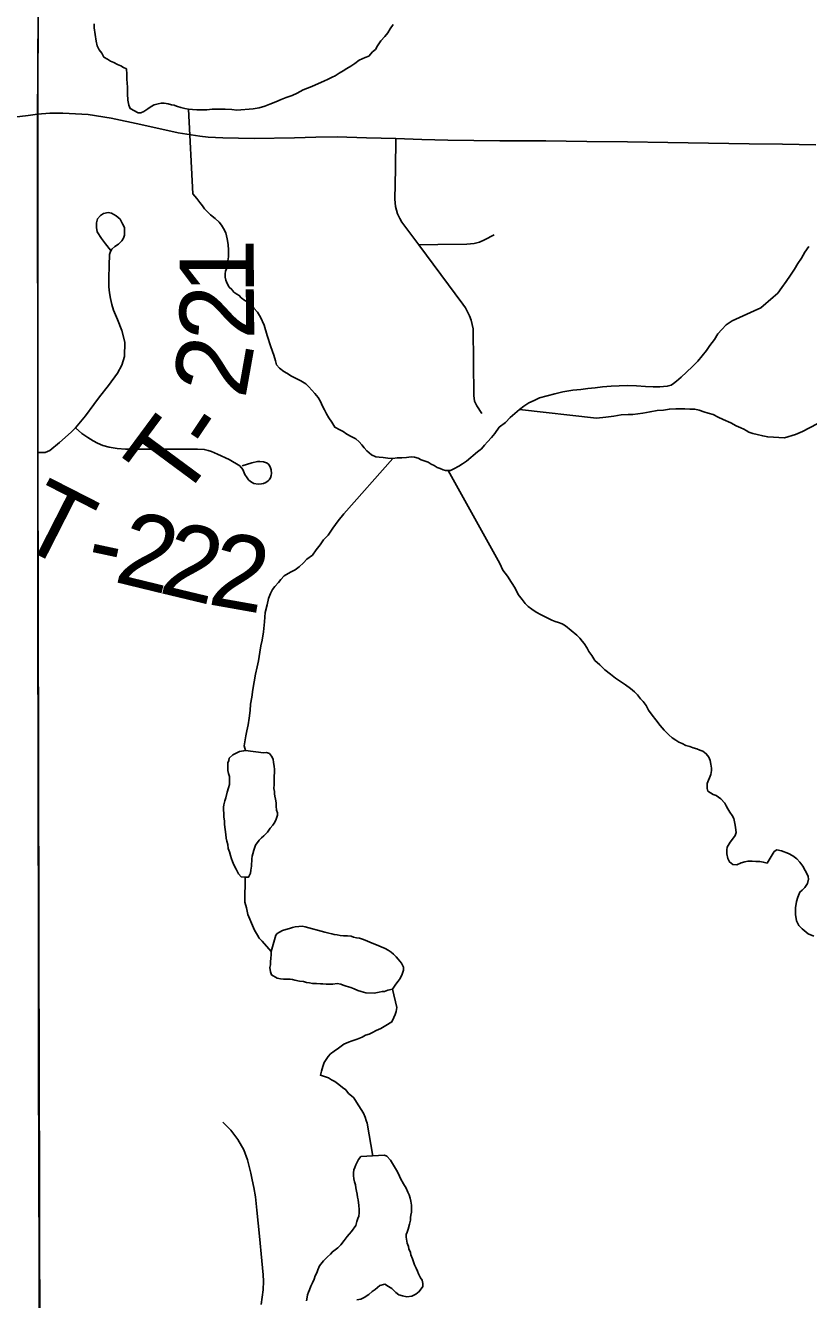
# Model space of a CAD drawing. Extents: x 103424 to 286016, y 38711 to 110967.
# Drawn here: x 119588 to 122771, y 79687 to 84863 of the extents above; entities that cross this region are included whole.
import ezdxf

# ---------------------------------------------------------------- set-up
doc = ezdxf.new("R2010")
doc.units = 0
for name, color, linetype in [('GM_X_Corporation', 7, 'Continuous'), ('GM_X_Minor_Lake', 7, 'Continuous'), ('GM_X_Minor_River', 7, 'Continuous'), ('GM_X_Township_Road', 7, 'Continuous'), ('GM_X_Township_Road_Text', 7, 'Continuous')]:
    doc.layers.add(name, color=color, linetype=linetype)

msp = doc.modelspace()

# ---------------------------------------------------------------- linework, layer by layer
at = {"layer": 'GM_X_Corporation'}
for points in [[(103423.7, 96534.8), (103423.7, 70904.9), (107977, 70917.3), (117928.9, 70934.4), (117946.9, 70934.9), (119688.2, 70990.2), (119635, 74016.7), (119631.7, 75117.1), (119628.6, 75451.2), (119621.3, 75805.1), (119622.8, 76073.8), (119627.2, 76341.1), (119628.6, 76885.8), (119631.6, 77245.6), (119644.2, 78899.8), (119644.5, 79431.3), (119642.9, 80216.4), (119641.6, 80653.5), (119641.6, 81200.9), (119640.3, 81697.7), (119639, 82590.1), (119639, 83128.3), (119639, 84504.6), (119641.6, 85722.3)], [(119688.2, 70990.2), (119635, 74016.7), (119631.7, 75117.1), (119628.6, 75451.2), (119621.3, 75805.1), (119622.8, 76073.8), (119627.2, 76341.1), (119628.6, 76885.8), (119631.6, 77245.6), (119644.2, 78899.8), (119644.5, 79431.3), (119642.9, 80216.4), (119641.6, 80653.5), (119641.6, 81200.9), (119640.3, 81697.7), (119639, 82590.1), (119639, 83128.3), (119639, 84504.6), (119641.6, 85722.3)]]:
    msp.add_lwpolyline(points, dxfattribs=at)
at = {"layer": 'GM_X_Minor_Lake'}
for points in [[(120482.7, 81917.6), (120474.6, 81915.5), (120458.5, 81913.3), (120430.4, 81898.9), (120416.4, 81886.6), (120414.5, 81876.5), (120410.6, 81866.4), (120410.8, 81852.2), (120410.9, 81836.1), (120413.1, 81824), (120417.3, 81811.9), (120417.4, 81801.8), (120417.5, 81791.7), (120417.6, 81779.6), (120413.8, 81765.4), (120407.9, 81747.2), (120402.1, 81724.9), (120398.2, 81712.7), (120394.4, 81696.5), (120392.5, 81686.4), (120392.6, 81674.3), (120394.8, 81662.2), (120395, 81646), (120397.1, 81631.9), (120397.3, 81615.8), (120399.6, 81595.6), (120401.8, 81575.4), (120404, 81561.3), (120406.2, 81549.2), (120410.4, 81535.1), (120412.6, 81519), (120416.8, 81504.9), (120421, 81490.8), (120425.2, 81476.7), (120429.4, 81466.6), (120435.6, 81452.5), (120443.9, 81434.4), (120454.2, 81416.4), (120464.4, 81404.3), (120480.6, 81402.5), (120494.7, 81402.6), (120502.6, 81418.9), (120504.5, 81431), (120506.3, 81447.2), (120506.2, 81457.3), (120508.1, 81467.4), (120508, 81477.5), (120509.9, 81487.6), (120511.8, 81497.7), (120515.7, 81511.9), (120523.5, 81532.2), (120537.4, 81552.5), (120547.4, 81562.7), (120557.4, 81570.9), (120571.4, 81585.2), (120583.3, 81601.5), (120593.3, 81613.7), (120601.2, 81625.9), (120607.1, 81638), (120613, 81654.3), (120612.9, 81664.4), (120608.7, 81674.4), (120606.5, 81690.6), (120606.4, 81704.7), (120604.2, 81718.8), (120602, 81730.9), (120599.9, 81741), (120599.8, 81751.1), (120597.6, 81763.2), (120599.4, 81779.4), (120599.2, 81799.6), (120599, 81813.7), (120600.9, 81825.9), (120600.7, 81840), (120598.6, 81854.1), (120596.4, 81868.2), (120594.2, 81882.4), (120588, 81894.4), (120579.8, 81904.4), (120567.6, 81908.4), (120555.6, 81908.2)], [(120555.6, 81908.2), (120482.7, 81917.6)], [(120606.3, 81166.4), (120587.1, 81100.5), (120587.2, 81088.4), (120585.4, 81072.2), (120583.5, 81060.1), (120583.7, 81046), (120581.8, 81035.8), (120584, 81017.7), (120588.2, 81005.6), (120610.6, 80991.7), (120624.7, 80989.8), (120636.9, 80987.9), (120651, 80988), (120663.1, 80988.2), (120673.3, 80986.2), (120683.4, 80984.3), (120701.6, 80980.5), (120717.8, 80978.6), (120729.9, 80974.7), (120742.1, 80972.8), (120754.2, 80970.9), (120770.4, 80971.1), (120786.6, 80969.2), (120796.6, 80969.3), (120810.8, 80967.4), (120822.9, 80967.5), (120837.1, 80967.7), (120855.2, 80969.9), (120869.4, 80968), (120879.5, 80964.1), (120891.7, 80960.1), (120909.9, 80954.3), (120924.1, 80948.3), (120938.3, 80942.4), (120952.5, 80938.5), (120970.8, 80932.7), (121005.1, 80931), (121025.3, 80935.2), (121037.4, 80937.4), (121047.5, 80937.4), (121061.5, 80943.7), (121079.7, 80947.9), (121093.5, 80968.2), (121103.5, 80980.4), (121111.5, 80990.6), (121119.3, 81008.9), (121125.2, 81025.1), (121125.1, 81037.2), (121116.8, 81053.3), (121102.5, 81069.3), (121094.3, 81079.3), (121084.1, 81089.3), (121073.9, 81097.3), (121061.7, 81105.3), (121049.5, 81113.2), (121033.2, 81119.1), (121015, 81127), (120996.7, 81134.9), (120978.4, 81142.8), (120962.2, 81148.7), (120946, 81154.6), (120933.8, 81156.5), (120921.7, 81158.4), (120911.6, 81162.3), (120897.4, 81164.2), (120881.2, 81164), (120867.1, 81165.9), (120854.9, 81167.8), (120842.8, 81169.7), (120832.7, 81171.7), (120820.5, 81175.6), (120804.3, 81179.5), (120790.1, 81183.3), (120739.5, 81197), (120725.3, 81200.9), (120713.1, 81202.8), (120699, 81202.6), (120684.9, 81200.5), (120672.8, 81198.4), (120660.7, 81194.2), (120646.6, 81190), (120632.6, 81185.8), (120620.5, 81179.6), (120610.5, 81173.5), (120606.3, 81166.4)], [(120606.3, 81166.4), (120587.1, 81100.5), (120587.2, 81088.4), (120585.4, 81072.2), (120583.5, 81060.1), (120583.7, 81046), (120581.8, 81035.8), (120584, 81017.7), (120588.2, 81005.6), (120610.6, 80991.7), (120624.7, 80989.8), (120636.9, 80987.9), (120651, 80988), (120663.1, 80988.2), (120673.3, 80986.2), (120683.4, 80984.3), (120701.6, 80980.5), (120717.8, 80978.6), (120729.9, 80974.7), (120742.1, 80972.8), (120754.2, 80970.9), (120770.4, 80971.1), (120786.6, 80969.2), (120796.6, 80969.3), (120810.8, 80967.4), (120822.9, 80967.5), (120837.1, 80967.7), (120855.2, 80969.9), (120869.4, 80968), (120879.5, 80964.1), (120891.7, 80960.1), (120909.9, 80954.3), (120924.1, 80948.3), (120938.3, 80942.4), (120952.5, 80938.5), (120970.8, 80932.7), (121005.1, 80931), (121025.3, 80935.2), (121037.4, 80937.4), (121047.5, 80937.4), (121061.5, 80943.7), (121079.7, 80947.9), (121093.5, 80968.2)], [(121093.5, 80968.2), (121103.5, 80980.4), (121111.5, 80990.6), (121119.3, 81008.9), (121125.2, 81025.1), (121125.1, 81037.2), (121116.8, 81053.3), (121102.5, 81069.3), (121094.3, 81079.3), (121084.1, 81089.3), (121073.9, 81097.3), (121061.7, 81105.3), (121049.5, 81113.2), (121033.2, 81119.1), (121015, 81127), (120996.7, 81134.9), (120978.4, 81142.8), (120962.2, 81148.7), (120946, 81154.6), (120933.8, 81156.5), (120921.7, 81158.4), (120911.6, 81162.3), (120897.4, 81164.2), (120881.2, 81164), (120867.1, 81165.9), (120854.9, 81167.8), (120842.8, 81169.7), (120832.7, 81171.7), (120820.5, 81175.6), (120804.3, 81179.5), (120790.1, 81183.3), (120739.5, 81197), (120725.3, 81200.9), (120713.1, 81202.8), (120699, 81202.6), (120684.9, 81200.5), (120672.8, 81198.4), (120660.7, 81194.2), (120646.6, 81190), (120632.6, 81185.8), (120620.5, 81179.6), (120610.5, 81173.5), (120606.3, 81166.4)], [(120951, 80267.1), (120942.3, 80255.7), (120930.4, 80233.3), (120926.5, 80223.2), (120922.6, 80213), (120920.7, 80200.9), (120920.8, 80190.8), (120923, 80176.7), (120925.1, 80164.6), (120929.3, 80152.5), (120931.5, 80140.4), (120933.7, 80126.3), (120935.8, 80114.2), (120938, 80102.1), (120940.1, 80092), (120942.3, 80079.9), (120942.4, 80069.8), (120944.6, 80051.7), (120944.8, 80039.5), (120942.9, 80025.4), (120939, 80015.2), (120935.1, 80003.1)], [(120934.7, 79685.9), (120950.9, 79688.1), (120964.9, 79694.3), (120983, 79706.6), (120996.9, 79718.9), (121009, 79727.1), (121029, 79743.4), (121049.1, 79749.7), (121063.4, 79739.7), (121077.6, 79731.8), (121093.9, 79715.8), (121106.2, 79705.8), (121120.4, 79701.9), (121138.6, 79698.1), (121158.7, 79700.3), (121174.8, 79708.5), (121188.8, 79718.8), (121202.7, 79739.1), (121202.6, 79751.2), (121200.4, 79765.3), (121194.2, 79775.4), (121186, 79791.5), (121181.8, 79801.5), (121175.6, 79813.6), (121169.4, 79827.7), (121165.2, 79839.7), (121161, 79851.8), (121154.8, 79867.9), (121152.6, 79878), (121146.4, 79892.1), (121144.3, 79902.1), (121140.1, 79916.2), (121135.8, 79940.4), (121135.6, 79950.5), (121139.6, 79960.7), (121143.5, 79972.8), (121149.3, 79993.1), (121153.1, 80009.3), (121153, 80019.4), (121154.9, 80029.5), (121156.8, 80041.7), (121156.6, 80057.8), (121156.5, 80069.9), (121154.3, 80086.1), (121152.1, 80098.2), (121147.9, 80112.3), (121141.7, 80122.3), (121135.5, 80138.4), (121125.2, 80156.5), (121112.8, 80178.6), (121104.5, 80196.7), (121096.3, 80212.8), (121071.5, 80252.9), (121057.2, 80268.9), (121047.1, 80272.9), (120951, 80267.1)], [(120935.1, 80003.1), (120931.2, 79986.9), (120913.3, 79962.5), (120903.4, 79952.3), (120895.4, 79942.1), (120883.5, 79925.8), (120869.5, 79909.5), (120857.5, 79897.3), (120847.5, 79889.1), (120835.5, 79880.9), (120827.6, 79870.7), (120815.6, 79860.5), (120799.6, 79844.2), (120783.7, 79823.8), (120775.8, 79807.6), (120771.9, 79795.4), (120766, 79783.2), (120762.1, 79769.1), (120754.2, 79754.8), (120748.3, 79740.6), (120742.4, 79726.5), (120738.5, 79716.3), (120734.5, 79706.2), (120732.6, 79696), (120730.8, 79681.9)]]:
    msp.add_lwpolyline(points, dxfattribs=at)
at = {"layer": 'GM_X_Minor_River'}
for points in [[(119866.8, 84868.8), (119867, 84852.7), (119875.7, 84798.2), (119880, 84780.1), (119888.2, 84764), (119898.5, 84750), (119906.8, 84733.9), (119921, 84725.9), (119933.2, 84718), (119947.4, 84712.1), (119961.6, 84704.1), (119975.8, 84698.2), (119986, 84692.3), (119998.2, 84686.3), (120000.5, 84664.1), (120000.7, 84643.9), (120003.1, 84611.6), (120003.4, 84585.4), (120003.7, 84559.1), (120008, 84538.9), (120014.2, 84524.9), (120046.7, 84507), (120056.8, 84507.1), (120068.9, 84513.3), (120084.9, 84523.5), (120098.9, 84533.8), (120111, 84540), (120127.1, 84544.2), (120139.2, 84546.3), (120151.3, 84546.4), (120167.5, 84544.6), (120181.7, 84540.7), (120191.8, 84538.8), (120201.9, 84534.8), (120220.2, 84528.9), (120236.4, 84525.1), (120250.5, 84523.2), (120266.7, 84521.3), (120284.9, 84519.5), (120305.1, 84519.7), (120325.3, 84519.9), (120347.5, 84522.1), (120371.7, 84522.4), (120400, 84522.6), (120426.3, 84520.9), (120446.5, 84519.1), (120513.1, 84523.8), (120537.3, 84528), (120561.4, 84534.3), (120581.5, 84542.6), (120605.7, 84553), (120627.8, 84561.3), (120647.9, 84569.5), (120672, 84577.9), (120692.1, 84588.2), (120716.2, 84600.5), (120752.4, 84615), (120778.5, 84627.4), (120800.6, 84635.7), (120818.7, 84644), (120834.7, 84652.2), (120846.8, 84658.4), (120862.8, 84668.6), (120878.9, 84678.9), (120894.9, 84687.1), (120911, 84697.4), (120927, 84707.7), (120945, 84722), (120969.1, 84732.3), (120983.2, 84738.5), (120999.2, 84754.8), (121011.2, 84765.1), (121019.1, 84779.3), (121033, 84799.6), (121048.9, 84818), (121060.9, 84832.2), (121070.8, 84848.5), (121082.7, 84866.8)], [(120250.5, 84523.2), (120268.7, 84177.9), (120285, 84159.9), (120297.3, 84143.9), (120307.6, 84129.8), (120315.8, 84117.8), (120328.1, 84105.8), (120340.3, 84093.8), (120358.7, 84077.8), (120375, 84063.8), (120385.3, 84051.8), (120393.5, 84037.8), (120401.8, 84019.7), (120408.1, 83995.5), (120412.4, 83973.3), (120412.7, 83949.1), (120413, 83922.8), (120411.2, 83906.6), (120407.3, 83890.4), (120405.5, 83874.3), (120401.6, 83864.1), (120399.7, 83854), (120399.8, 83839.9), (120402, 83827.8), (120408.2, 83813.7), (120416.5, 83799.6), (120426.7, 83789.6), (120434.9, 83779.6), (120447.1, 83771.6), (120457.2, 83765.7), (120465.4, 83755.7), (120479.7, 83745.7), (120491.9, 83737.8), (120506.2, 83727.8), (120516.4, 83713.8), (120530.7, 83697.7), (120543.1, 83677.7), (120557.6, 83645.5), (120570.2, 83603.2), (120584.9, 83556.9), (120597.4, 83522.7), (120603.7, 83500.5), (120607.9, 83484.4), (120620.2, 83470.4), (120638.6, 83456.4), (120650.7, 83450.5), (120669.1, 83438.5), (120707.7, 83418.7), (120728, 83406.8), (120740.3, 83394.8), (120752.5, 83380.8), (120764.8, 83366.8), (120777.1, 83350.7), (120787.4, 83334.7), (120795.7, 83316.6), (120804, 83300.5), (120812.2, 83284.4), (120820.5, 83268.3), (120832.8, 83250.3), (120845.2, 83230.2), (120865.5, 83220.3), (120879.7, 83212.4), (120894, 83202.4), (120912.3, 83192.5), (120930.6, 83182.6), (120944.8, 83170.6), (120955.1, 83158.6), (120965.3, 83146.5), (120975.5, 83134.5), (120993.9, 83118.5), (121012.2, 83110.6), (121026.3, 83108.8), (121042.5, 83106.9), (121060.7, 83105.1), (121080.9, 83103.3), (121099.1, 83105.5), (121117.2, 83105.6), (121137.4, 83107.9), (121155.6, 83110), (121169.7, 83108.2), (121183.9, 83104.3), (121196.1, 83098.3), (121212.3, 83092.4), (121224.5, 83088.5), (121236.7, 83080.6), (121248.9, 83074.6), (121261.1, 83066.7), (121273.3, 83062.8), (121285.5, 83056.8), (121295.6, 83054.9), (121305.7, 83055), (121315.8, 83055.1), (121329.8, 83061.3), (121349.9, 83071.6), (121363.9, 83081.8), (121380, 83092.1), (121426, 83130.9), (121442, 83143.2)], [(121442, 83143.2), (121453.9, 83157.5), (121465.9, 83171.7), (121481.9, 83188), (121495.8, 83204.3), (121513.7, 83230.8), (121539.7, 83249.2), (121557.7, 83269.6), (121577.7, 83286), (121595.7, 83302.3), (121613.7, 83316.6), (121633.7, 83328.9), (121655.8, 83339.2), (121677.9, 83349.6), (121708.1, 83358), (121740.3, 83366.4), (121772.6, 83374.8), (121812.9, 83381.2), (121845.2, 83383.6), (121873.4, 83387.9), (121903.7, 83390.2), (121933.9, 83394.5), (121968.2, 83396.9), (122000.5, 83399.2), (122036.8, 83399.6), (122071.2, 83397.9), (122107.6, 83396.3), (122139.9, 83394.6), (122166.2, 83394.8), (122196.4, 83397.1), (122212.5, 83401.4), (122222.6, 83407.5), (122234.6, 83417.7), (122252.6, 83434.1), (122274.5, 83454.5), (122298.5, 83476.9), (122320.5, 83499.4), (122338.4, 83519.8), (122356.3, 83542.2), (122370.2, 83562.5), (122388.1, 83586.9), (122402, 83609.3), (122417.9, 83627.6), (122435.9, 83646), (122460, 83662.4), (122490.1, 83676.8), (122520.2, 83689.2), (122550.4, 83703.7), (122576.5, 83716.1), (122626.5, 83759), (122646.5, 83775.3), (122662.4, 83797.7), (122680.3, 83822.1), (122698.1, 83848.6), (122714, 83873), (122727.9, 83895.3), (122741.8, 83917.7), (122755.6, 83942.1), (122771.5, 83964.4)], [(121595.7, 83302.3), (121909.1, 83267), (121947.5, 83271.5), (121979.7, 83275.8), (122009.9, 83280.1), (122038.2, 83282.5), (122056.4, 83282.6), (122096.7, 83287.1), (122126.9, 83293.4), (122155.2, 83297.7), (122181.4, 83300), (122205.6, 83304.3), (122231.8, 83304.6), (122250, 83304.8), (122268.2, 83304.9), (122288.4, 83303.1), (122308.6, 83303.3), (122326.8, 83299.5), (122345.1, 83293.6), (122363.3, 83287.7), (122383.6, 83281.8), (122403.9, 83271.9), (122424.2, 83262), (122454.7, 83248.2), (122477, 83236.3), (122495.3, 83228.4), (122507.5, 83222.5), (122517.6, 83216.5), (122527.8, 83210.6), (122544, 83204.7), (122562.3, 83200.8), (122584.5, 83195), (122604.8, 83191.1), (122673.5, 83187.8), (122717.8, 83200.3), (122745.9, 83212.7), (122806.1, 83243.6)], [(121080.9, 83103.3), (120881.6, 82879.1), (120859.7, 82850.6), (120837.8, 82820), (120817.9, 82791.6), (120800, 82773.2), (120786.1, 82752.9), (120770.2, 82732.5), (120754.3, 82710.1), (120732.2, 82693.8), (120718.2, 82679.5), (120700.3, 82663.1), (120684.3, 82650.9), (120668.2, 82642.6), (120656.1, 82636.4), (120640.1, 82626.2), (120626.1, 82611.9), (120616.2, 82599.7), (120602.2, 82583.4), (120592.3, 82571.2), (120584.4, 82554.9), (120576.5, 82534.6), (120570.8, 82508.3), (120563, 82478), (120559.5, 82439.5), (120555.9, 82399.1), (120550.2, 82364.7), (120544.4, 82342.4), (120540.7, 82316.1), (120535, 82281.7), (120529.3, 82257.4), (120523.5, 82227.1), (120517.8, 82196.7), (120512.2, 82164.3), (120508.5, 82134), (120502.7, 82105.7), (120501, 82079.4), (120497.3, 82049), (120493.6, 82020.7), (120487.9, 81996.4), (120484, 81976.2), (120476.4, 81935.7), (120482.7, 81917.6)], [(121305.7, 83055), (121516.1, 82677.3), (121528.5, 82649.2), (121547, 82625.1), (121563.4, 82599), (121577.8, 82576.9), (121590.2, 82550.8), (121606.6, 82530.7), (121618.9, 82514.7), (121631.2, 82502.7), (121645.5, 82490.7), (121663.8, 82478.8), (121684.1, 82468.9), (121706.4, 82457), (121726.8, 82447.1), (121741, 82441.2), (121755.1, 82437.3), (121769.3, 82431.4), (121783.6, 82423.4), (121828.5, 82385.5), (121840.7, 82373.5), (121850.9, 82361.5), (121859.1, 82351.5), (121871.5, 82333.4), (121877.7, 82319.3), (121890, 82303.3), (121902.3, 82283.2), (121922.8, 82265.2), (121943.2, 82245.2), (121965.6, 82227.3), (121986, 82211.3), (122006.3, 82197.4), (122026.7, 82183.4), (122047.1, 82169.5), (122063.4, 82155.5), (122075.6, 82143.5), (122088, 82127.5), (122098.2, 82115.5), (122110.5, 82099.4), (122120.8, 82081.4), (122135.2, 82061.3), (122149.5, 82041.2), (122168, 82019.2), (122184.4, 81999.2), (122202.8, 81981.2), (122217, 81969.2), (122231.3, 81959.2), (122243.5, 81951.3), (122257.7, 81945.4), (122271.9, 81937.4), (122288.1, 81933.5), (122302.3, 81927.6), (122316.5, 81923.7), (122328.7, 81917.8), (122340.9, 81913.9), (122355.1, 81903.9), (122365.4, 81889.9), (122371.6, 81875.8), (122373.8, 81861.7), (122376, 81845.5), (122376.1, 81835.4), (122374.3, 81819.3), (122358.5, 81782.7), (122358.8, 81762.5), (122360.9, 81752.5), (122383.3, 81738.6), (122395.5, 81734.6), (122413.8, 81720.7), (122430.2, 81702.6), (122436.3, 81692.6), (122442.5, 81680.6), (122450.8, 81666.5), (122461, 81652.5), (122467.2, 81640.4), (122471.5, 81620.2), (122473.7, 81606.1), (122475.9, 81594), (122476, 81583.9), (122472.1, 81571.8), (122462.1, 81557.5), (122452.2, 81545.3), (122440.3, 81525), (122438.4, 81512.9), (122438.6, 81496.7), (122442.9, 81478.5), (122449.1, 81464.5), (122463.3, 81454.5), (122479.5, 81452.7), (122497.6, 81460.9), (122511.7, 81465.1), (122523.8, 81467.2), (122542, 81467.4), (122556.1, 81465.5), (122572.3, 81465.7), (122586.4, 81463.8), (122602.6, 81459.9), (122630.4, 81506.7), (122642.4, 81512.9), (122660.6, 81509), (122689, 81499.2), (122707.3, 81489.3)], [(122707.3, 81489.3), (122723.6, 81477.3), (122735.9, 81463.3), (122748.2, 81447.3), (122756.5, 81429.2), (122764.7, 81415.1), (122768.9, 81405), (122771, 81395), (122767.2, 81376.7), (122755.3, 81360.5), (122745.3, 81350.3), (122735.3, 81342.1), (122727.4, 81321.8), (122721.6, 81303.6), (122717.9, 81277.3), (122718.1, 81251), (122722.5, 81224.8), (122730.8, 81206.7), (122745.1, 81192.7), (122769.6, 81172.7), (122791.9, 81162.9)], [(120480.6, 81402.5), (120479.7, 81301.5), (120486.1, 81277.3), (120492.4, 81251.1), (120515.3, 81196.8), (120519.4, 81186.7), (120531.8, 81166.6), (120538, 81154.6), (120550.3, 81142.6), (120587.1, 81100.5)], [(121097.1, 80872.8), (121079.7, 80947.9)], [(121097.1, 80872.8), (121094.8, 80857.1), (121090.9, 80845), (121085, 80832.8), (121077.2, 80814.5), (121053.1, 80800.1), (121033, 80787.8), (121012.9, 80779.5), (120998.9, 80771.3), (120984.8, 80765.1), (120970.7, 80760.9), (120956.7, 80752.7), (120936.6, 80744.4), (120916.5, 80738.2), (120900.4, 80732), (120882.3, 80723.7), (120860.3, 80707.3), (120842.2, 80695), (120828.2, 80684.8), (120818.2, 80674.6), (120810.3, 80662.4), (120802.4, 80650.2), (120796.5, 80634), (120790.7, 80613.7), (120786.8, 80597.5), (120807.1, 80591.7), (120819.2, 80587.7), (120831.5, 80579.8), (120845.7, 80571.8), (120862, 80559.9), (120876.3, 80547.9), (120890.5, 80537.9), (120900.8, 80523.9), (120913, 80513.9), (120923.2, 80505.9), (120933.5, 80487.9), (120962.3, 80443.7), (120968.5, 80427.6), (120972.7, 80413.5), (120976.9, 80403.5), (121000.1, 80269.1)]]:
    msp.add_lwpolyline(points, dxfattribs=at)
at = {"layer": 'GM_X_Township_Road'}
for points in [[(119644.5, 78894.7), (119645, 79059.8), (119645.4, 79224.9), (119645.9, 79373.4), (119646.3, 79522), (119645.9, 79687), (119645.6, 79852.1), (119644.6, 80290.5), (119644.2, 80455.6), (119643.7, 80620.6), (119643.3, 80785.7), (119642.8, 80950.8), (119642.1, 81199.9), (119640.9, 81860.2), (119638.6, 83127.2), (119637.6, 84501.8), (119638.3, 84666.9), (119639.1, 84831.9), (119639.6, 84957.7)], [(119483.7, 84483.4), (119598.7, 84496.6), (119637.6, 84501.8)], [(119637.6, 84501.8), (119687.6, 84506.5), (119740.2, 84505.8), (119843.3, 84500.2), (119936.2, 84486.4), (120057, 84460), (120208.9, 84426.5), (120296.2, 84413.2), (120331, 84409.2), (120390.5, 84406.1), (120517.2, 84403.3), (120682.2, 84406.7), (120768.5, 84408.5), (120854.9, 84410.2), (120974, 84406.5), (121093.2, 84402.8), (121199.1, 84399.6), (121305.1, 84396.4), (121410.8, 84394.8), (121516.5, 84393.3), (121609.5, 84393.8), (121702.6, 84394.3), (121786, 84393.1), (121869.4, 84391.8), (122034.4, 84389.3), (122199.5, 84386.8), (122364.5, 84384.3), (122529.5, 84381.8), (122664.9, 84379.7), (122800.4, 84377.7)], [(121443.3, 83286.7), (121422, 83317.1), (121413.8, 83336.6), (121409.9, 83358.8), (121407.4, 83630.1), (121404.2, 83647.9), (121399.2, 83665.4), (121392.9, 83682.5), (121385.3, 83699), (121376.3, 83714.8), (121366, 83729.8), (121276.2, 83850.6), (121186.4, 83971.4), (121117.9, 84063.5), (121109.4, 84077.7), (121100.6, 84097.4), (121095.8, 84111.8), (121092.5, 84126.7), (121090.5, 84141.9), (121090, 84157.1), (121091.6, 84279.9), (121093.2, 84402.8)], [(119638.6, 83127.2), (119667.8, 83128), (119687.5, 83136), (119726.6, 83168.8), (119774.4, 83209.8), (119791.5, 83228.4), (119832.3, 83276.9), (119866, 83323.2), (119888.4, 83353.3), (119925.9, 83399.9), (119962.1, 83450.5), (119979.8, 83483.1), (119990.6, 83518.4), (119991.4, 83575.9), (119979.4, 83622.9), (119961.5, 83668.2), (119946.5, 83706.2), (119939.7, 83729.2), (119934.1, 83752.7), (119930.1, 83776.4), (119927.4, 83800.3), (119926.4, 83836.4), (119928.2, 83887.2), (119930.3, 83931.8), (119933.3, 83943.7), (119938.6, 83953.2), (119951.2, 83964.1), (119965.6, 83974.6), (119979.3, 83987.1), (119986.1, 83998.9), (119990.3, 84011.1), (119991, 84023.9), (119990.6, 84042), (119983, 84057.3), (119972.5, 84075.4), (119956.9, 84088.6), (119937.6, 84099.5), (119924.7, 84102.7), (119905, 84098.7), (119892.9, 84090.7), (119881.3, 84077), (119876.9, 84061.3), (119877.3, 84041.6), (119880.1, 84024.3), (119897, 83997.4), (119913, 83975.8), (119934.1, 83950.2)], [(121186.4, 83971.4), (121264.6, 83972.6), (121382.5, 83974.6), (121412.3, 83977), (121433.3, 83982.4), (121453.8, 83991.2), (121492.9, 84012.2)], [(119791.5, 83228.4), (119817.8, 83204.6), (119841.1, 83188.1), (119863.2, 83174.6), (119881.2, 83165.8), (119902.9, 83156.2), (119928.7, 83148.8), (119960.3, 83144.4), (119994.6, 83141.5), (120086.2, 83140.7), (120287.2, 83141.3), (120314.7, 83140.4), (120330.8, 83136), (120344.1, 83132), (120368.1, 83121.5), (120416.5, 83098.8), (120460, 83073.4), (120471, 83058.3), (120480, 83037.8), (120489.6, 83024.2), (120494.9, 83016.5), (120503, 83009.7), (120515.8, 83001.6), (120534.3, 82999.1), (120547.4, 83000.1), (120556, 83001.6), (120565.6, 83005.7), (120574, 83012), (120578.4, 83017.1), (120583.7, 83025.4), (120586.9, 83034), (120587.8, 83042.2), (120586.5, 83056.7), (120584.3, 83066), (120579.9, 83074.5), (120575.1, 83081.1), (120567.4, 83085.9), (120554.9, 83090), (120540.9, 83091.4), (120530.6, 83090.7), (120507.8, 83086.3), (120469.2, 83073.2)], [(120545.6, 79665.8), (120554.1, 79726), (120555.4, 79760.8), (120554.1, 79787), (120548.6, 79844.1), (120538.8, 79944.2), (120528.5, 80049.8), (120522.7, 80104.2), (120515.8, 80141.9), (120509.8, 80173.1), (120504.5, 80199.8), (120491.2, 80254.3), (120476.1, 80295), (120450.6, 80336.9), (120422.4, 80374.9), (120390.9, 80407)]]:
    msp.add_lwpolyline(points, dxfattribs=at)

# ---------------------------------------------------------------- texts
at = {"layer": 'GM_X_Township_Road_Text'}
for s, rotation, p in [('1', 90.0781, (120516.4, 83771.9)), ('2', 90.6233, (120518.4, 83586.7)), ('2', 79.916, (120480.8, 83342.4)), ('T', 53.5192, (120218.2, 82919.7)), ('-', 56.2171, (120361.4, 83114)), ('T', 332.9788, (119541.7, 82760.6)), ('2', 346.3298, (119942.7, 82603.9)), ('2', 346.5249, (120124.5, 82559.7)), ('2', 349.9369, (120324.5, 82512.4)), ('-', 347.9594, (119823.7, 82629.3))]:
    msp.add_text(s, height=301.9, rotation=rotation, dxfattribs=at).set_placement(p)

doc.saveas('drawing.dxf')
